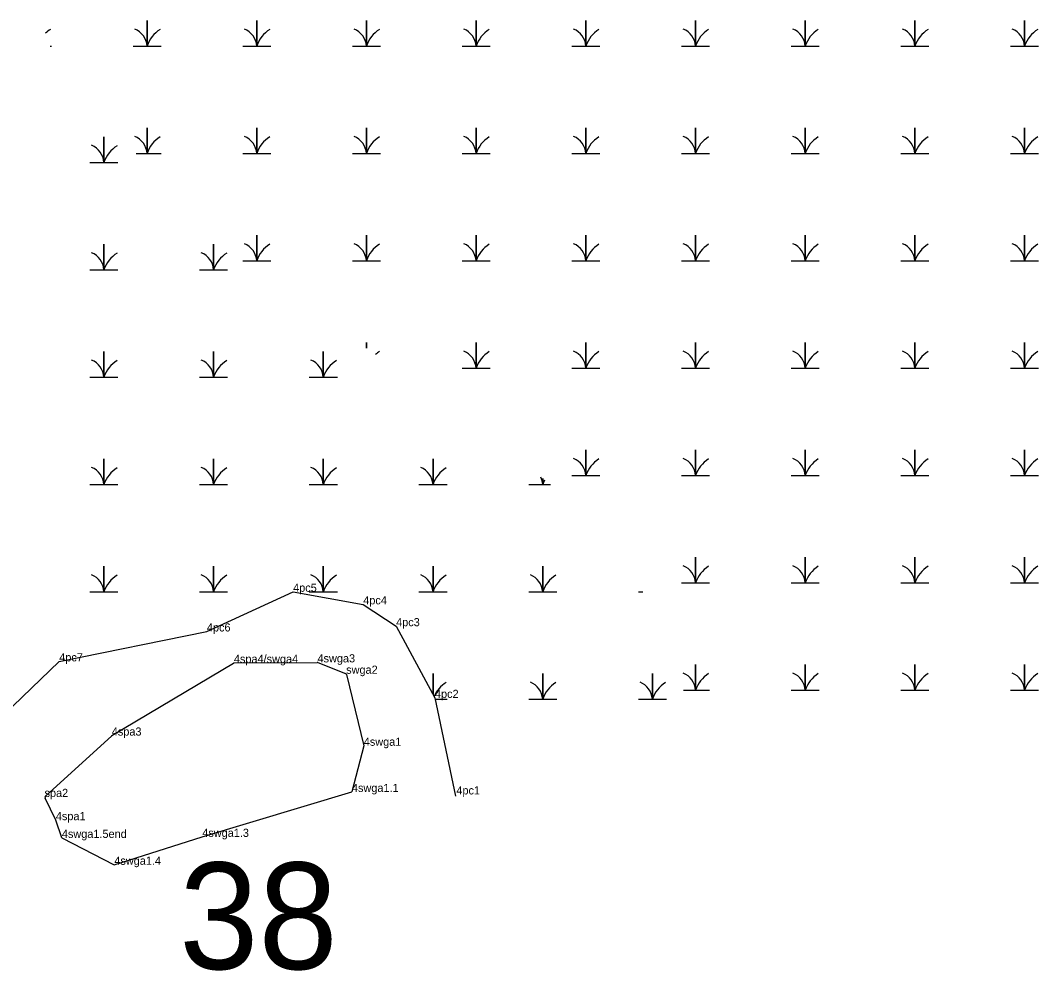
# Model space of a CAD drawing. Extents: x 2072529 to 2268796, y 436423 to 470397.
# Drawn here: x 2104808 to 2105432, y 455716 to 456299 of the extents above; entities that cross this region are included whole.
import ezdxf

# ---------------------------------------------------------------- set-up
doc = ezdxf.new("R2010")
doc.units = 0
for name, color, linetype in [('Default', 7, 'Continuous'), ('Exist Environmental Wetland Boundary', 7, 'Continuous'), ('Exist Environmental Wetland Boundary Cogo Comment', 7, 'Continuous'), ('Exist Environmental Wetland Boundary Cogo Point CELL', 7, 'Continuous'), ('Exist Hydro Jurisdictional Stream or Body of Water NEU Mitigable', 7, 'Continuous'), ('Exist Hydro Jurisdictional Stream or Body of Water NEU Mitigable Cogo Comment', 7, 'Continuous'), ('Exist Hydro Swamp or Marsh', 7, 'Continuous')]:
    doc.layers.add(name, color=color, linetype=linetype)

msp = doc.modelspace()

# ---------------------------------------------------------------- linework, layer by layer
at = {"layer": 'Exist Environmental Wetland Boundary'}
msp.add_lwpolyline([(2104609.24, 455735.62), (2104621.06, 455780.18), (2104644.33, 455777.94), (2104722.37, 455817.34), (2104735.27, 455837.55), (2104752.11, 455850.33), (2104763.03, 455846.4), (2104748.18, 455876.1), (2104755.02, 455879.71), (2104763.33, 455856.41), (2104791.87, 455867.62), (2104831.75, 455905.88), (2104922.28, 455924.22), (2104975.15, 455948.56), (2105018.14, 455940.86), (2105038.3, 455927.43), (2105062.1, 455883.49), (2105074.69, 455823.25)], dxfattribs=at)
at = {"layer": 'Exist Environmental Wetland Boundary Cogo Point CELL'}
for p, q in [((2104975.15, 455948.56), (2104975.15, 455948.56)), ((2105018.14, 455940.86), (2105018.14, 455940.86)), ((2104922.28, 455924.22), (2104922.28, 455924.22)), ((2105038.3, 455927.43), (2105038.3, 455927.43)), ((2104831.75, 455905.88), (2104831.75, 455905.88)), ((2104938.82, 455904.92), (2104938.82, 455904.92)), ((2104990.09, 455905.27), (2104990.09, 455905.27)), ((2105007.67, 455898.3), (2105007.67, 455898.3)), ((2105062.1, 455883.49), (2105062.1, 455883.49)), ((2104863.97, 455860.4), (2104863.97, 455860.4)), ((2105018.46, 455854.16), (2105018.46, 455854.16)), ((2104822.73, 455822.78), (2104822.73, 455822.78)), ((2105011.2, 455825.84), (2105011.2, 455825.84)), ((2105074.69, 455823.25), (2105074.69, 455823.25)), ((2104829.66, 455808.56), (2104829.66, 455808.56)), ((2104833.36, 455797.69), (2104833.36, 455797.69)), ((2104919.44, 455798.31), (2104919.44, 455798.31)), ((2104865.51, 455781.23), (2104865.51, 455781.23))]:
    msp.add_line(p, q, dxfattribs=at)
at = {"layer": 'Exist Hydro Jurisdictional Stream or Body of Water NEU Mitigable'}
for p, q in [((2104864.06, 455860.45), (2104938.59, 455904.78)), ((2104939.09, 455904.92), (2104989.9, 455905.26)), ((2104990.27, 455905.19), (2105007.19, 455898.49)), ((2104823.29, 455823.28), (2104863.9, 455860.33))]:
    msp.add_line(p, q, dxfattribs=at)
for points in [[(2105007.79, 455897.8), (2105018.46, 455854.16), (2105011.2, 455825.84)], [(2104833.36, 455797.69), (2104865.51, 455781.23), (2104919.44, 455798.31), (2105011.2, 455825.84)], [(2104833.36, 455797.69), (2104829.66, 455808.56), (2104823.06, 455822.1)]]:
    msp.add_lwpolyline(points, dxfattribs=at)
for centre, start, end in [((2104939.1, 455903.92), 90.38443, 120.74544), ((2104989.9, 455904.26), 68.39894, 90.38443), ((2105006.82, 455897.57), 13.73502, 68.39894), ((2104864.57, 455859.59), 120.74544, 132.37312), ((2104823.96, 455822.54), 132.37312, 205.98818)]:
    msp.add_arc(centre, 1, start, end, dxfattribs=at)
at = {"layer": 'Exist Hydro Swamp or Marsh'}
for points in [[(2104877.01, 456283.01), (2104885.61, 456283.01), (2104885.61, 456298.79), (2104885.61, 456283.01), (2104894.22, 456283.01)], [(2104944.26, 456283.01), (2104952.86, 456283.01), (2104952.86, 456298.79), (2104952.86, 456283.01), (2104961.47, 456283.01)], [(2105011.51, 456283.01), (2105020.11, 456283.01), (2105020.11, 456298.79), (2105020.11, 456283.01), (2105028.72, 456283.01)], [(2105078.76, 456283.01), (2105087.36, 456283.01), (2105087.36, 456298.79), (2105087.36, 456283.01), (2105095.97, 456283.01)], [(2105146.01, 456283.01), (2105154.61, 456283.01), (2105154.61, 456298.79), (2105154.61, 456283.01), (2105163.22, 456283.01)], [(2105213.26, 456283.01), (2105221.86, 456283.01), (2105221.86, 456298.79), (2105221.86, 456283.01), (2105230.47, 456283.01)], [(2105280.51, 456283.01), (2105289.11, 456283.01), (2105289.11, 456298.79), (2105289.11, 456283.01), (2105297.72, 456283.01)], [(2105347.76, 456283.01), (2105356.36, 456283.01), (2105356.36, 456298.79), (2105356.36, 456283.01), (2105364.97, 456283.01)], [(2105415.01, 456283.01), (2105423.61, 456283.01), (2105423.61, 456298.79), (2105423.61, 456283.01), (2105432.22, 456283.01)], [(2104826.22, 456283.01), (2104826.97, 456283.01)], [(2104878.87, 456217.21), (2104885.61, 456217.21), (2104885.61, 456232.99), (2104885.61, 456217.21), (2104894.22, 456217.21)], [(2104944.26, 456217.21), (2104952.86, 456217.21), (2104952.86, 456232.99), (2104952.86, 456217.21), (2104961.47, 456217.21)], [(2105011.51, 456217.21), (2105020.11, 456217.21), (2105020.11, 456232.99), (2105020.11, 456217.21), (2105028.72, 456217.21)], [(2105078.76, 456217.21), (2105087.36, 456217.21), (2105087.36, 456232.99), (2105087.36, 456217.21), (2105095.97, 456217.21)], [(2105146.01, 456217.21), (2105154.61, 456217.21), (2105154.61, 456232.99), (2105154.61, 456217.21), (2105163.22, 456217.21)], [(2105213.26, 456217.21), (2105221.86, 456217.21), (2105221.86, 456232.99), (2105221.86, 456217.21), (2105230.47, 456217.21)], [(2105280.51, 456217.21), (2105289.11, 456217.21), (2105289.11, 456232.99), (2105289.11, 456217.21), (2105297.72, 456217.21)], [(2105347.76, 456217.21), (2105356.36, 456217.21), (2105356.36, 456232.99), (2105356.36, 456217.21), (2105364.97, 456217.21)], [(2105415.01, 456217.21), (2105423.61, 456217.21), (2105423.61, 456232.99), (2105423.61, 456217.21), (2105432.22, 456217.21)], [(2104850.56, 456211.72), (2104859.16, 456211.72), (2104859.16, 456227.5), (2104859.16, 456211.72), (2104867.76, 456211.72)], [(2104944.26, 456151.41), (2104952.86, 456151.41), (2104952.86, 456167.19), (2104952.86, 456151.41), (2104961.47, 456151.41)], [(2105011.51, 456151.41), (2105020.11, 456151.41), (2105020.11, 456167.19), (2105020.11, 456151.41), (2105028.72, 456151.41)], [(2105078.76, 456151.41), (2105087.36, 456151.41), (2105087.36, 456167.19), (2105087.36, 456151.41), (2105095.97, 456151.41)], [(2105146.01, 456151.41), (2105154.61, 456151.41), (2105154.61, 456167.19), (2105154.61, 456151.41), (2105163.22, 456151.41)], [(2105213.26, 456151.41), (2105221.86, 456151.41), (2105221.86, 456167.19), (2105221.86, 456151.41), (2105230.47, 456151.41)], [(2105280.51, 456151.41), (2105289.11, 456151.41), (2105289.11, 456167.19), (2105289.11, 456151.41), (2105297.72, 456151.41)], [(2105347.76, 456151.41), (2105356.36, 456151.41), (2105356.36, 456167.19), (2105356.36, 456151.41), (2105364.97, 456151.41)], [(2105415.01, 456151.41), (2105423.61, 456151.41), (2105423.61, 456167.19), (2105423.61, 456151.41), (2105432.22, 456151.41)], [(2104850.56, 456145.92), (2104859.16, 456145.92), (2104859.16, 456161.7), (2104859.16, 456145.92), (2104867.76, 456145.92)], [(2104917.81, 456145.92), (2104926.41, 456145.92), (2104926.41, 456161.7), (2104926.41, 456145.92), (2104935.01, 456145.92)], [(2105020.11, 456097.82), (2105020.11, 456101.39), (2105020.11, 456097.82)], [(2105078.76, 456085.61), (2105087.36, 456085.61), (2105087.36, 456101.39), (2105087.36, 456085.61), (2105095.97, 456085.61)], [(2105146.01, 456085.61), (2105154.61, 456085.61), (2105154.61, 456101.39), (2105154.61, 456085.61), (2105163.22, 456085.61)], [(2105213.26, 456085.61), (2105221.86, 456085.61), (2105221.86, 456101.39), (2105221.86, 456085.61), (2105230.47, 456085.61)], [(2105280.51, 456085.61), (2105289.11, 456085.61), (2105289.11, 456101.39), (2105289.11, 456085.61), (2105297.72, 456085.61)], [(2105347.76, 456085.61), (2105356.36, 456085.61), (2105356.36, 456101.39), (2105356.36, 456085.61), (2105364.97, 456085.61)], [(2105415.01, 456085.61), (2105423.61, 456085.61), (2105423.61, 456101.39), (2105423.61, 456085.61), (2105432.22, 456085.61)], [(2104850.56, 456080.12), (2104859.16, 456080.12), (2104859.16, 456095.9), (2104859.16, 456080.12), (2104867.76, 456080.12)], [(2104917.81, 456080.12), (2104926.41, 456080.12), (2104926.41, 456095.9), (2104926.41, 456080.12), (2104935.01, 456080.12)], [(2104985.06, 456080.12), (2104993.66, 456080.12), (2104993.66, 456095.9), (2104993.66, 456080.12), (2105002.26, 456080.12)], [(2105146.01, 456019.81), (2105154.61, 456019.81), (2105154.61, 456035.59), (2105154.61, 456019.81), (2105163.22, 456019.81)], [(2105213.26, 456019.81), (2105221.86, 456019.81), (2105221.86, 456035.59), (2105221.86, 456019.81), (2105230.47, 456019.81)], [(2105280.51, 456019.81), (2105289.11, 456019.81), (2105289.11, 456035.59), (2105289.11, 456019.81), (2105297.72, 456019.81)], [(2105347.76, 456019.81), (2105356.36, 456019.81), (2105356.36, 456035.59), (2105356.36, 456019.81), (2105364.97, 456019.81)], [(2105415.01, 456019.81), (2105423.61, 456019.81), (2105423.61, 456035.59), (2105423.61, 456019.81), (2105432.22, 456019.81)], [(2104850.56, 456014.32), (2104859.16, 456014.32), (2104859.16, 456030.1), (2104859.16, 456014.32), (2104867.76, 456014.32)], [(2104917.81, 456014.32), (2104926.41, 456014.32), (2104926.41, 456030.1), (2104926.41, 456014.32), (2104935.01, 456014.32)], [(2104985.06, 456014.32), (2104993.66, 456014.32), (2104993.66, 456030.1), (2104993.66, 456014.32), (2105002.26, 456014.32)], [(2105052.31, 456014.32), (2105060.91, 456014.32), (2105060.91, 456030.1), (2105060.91, 456014.32), (2105069.51, 456014.32)], [(2105119.56, 456014.32), (2105128.16, 456014.32), (2105128.16, 456017.89)], [(2105128.16, 456017.89), (2105128.16, 456014.32), (2105132.98, 456014.32)], [(2105213.26, 455954.01), (2105221.86, 455954.01), (2105221.86, 455969.79), (2105221.86, 455954.01), (2105230.47, 455954.01)], [(2105280.51, 455954.01), (2105289.11, 455954.01), (2105289.11, 455969.79), (2105289.11, 455954.01), (2105297.72, 455954.01)], [(2105347.76, 455954.01), (2105356.36, 455954.01), (2105356.36, 455969.79), (2105356.36, 455954.01), (2105364.97, 455954.01)], [(2105415.01, 455954.01), (2105423.61, 455954.01), (2105423.61, 455969.79), (2105423.61, 455954.01), (2105432.22, 455954.01)], [(2104850.56, 455948.52), (2104859.16, 455948.52), (2104859.16, 455964.3), (2104859.16, 455948.52), (2104867.76, 455948.52)], [(2104917.81, 455948.52), (2104926.41, 455948.52), (2104926.41, 455964.3), (2104926.41, 455948.52), (2104935.01, 455948.52)], [(2104985.06, 455948.52), (2104993.66, 455948.52), (2104993.66, 455964.3), (2104993.66, 455948.52), (2105002.26, 455948.52)], [(2105052.31, 455948.52), (2105060.91, 455948.52), (2105060.91, 455964.3), (2105060.91, 455948.52), (2105069.51, 455948.52)], [(2105119.56, 455948.52), (2105128.16, 455948.52), (2105128.16, 455964.3), (2105128.16, 455948.52), (2105136.76, 455948.52)], [(2105186.81, 455948.52), (2105189.64, 455948.52)], [(2105214.56, 455888.21), (2105221.86, 455888.21), (2105221.86, 455903.99), (2105221.86, 455888.21), (2105230.47, 455888.21)], [(2105280.51, 455888.21), (2105289.11, 455888.21), (2105289.11, 455903.99), (2105289.11, 455888.21), (2105297.72, 455888.21)], [(2105347.76, 455888.21), (2105356.36, 455888.21), (2105356.36, 455903.99), (2105356.36, 455888.21), (2105364.97, 455888.21)], [(2105415.01, 455888.21), (2105423.61, 455888.21), (2105423.61, 455903.99), (2105423.61, 455888.21), (2105432.22, 455888.21)], [(2105060.91, 455885.69), (2105060.91, 455898.5), (2105060.91, 455885.69)], [(2105119.56, 455882.72), (2105128.16, 455882.72), (2105128.16, 455898.5), (2105128.16, 455882.72), (2105136.76, 455882.72)], [(2105186.81, 455882.72), (2105195.41, 455882.72), (2105195.41, 455898.5), (2105195.41, 455882.72), (2105204.01, 455882.72)], [(2105062.26, 455882.72), (2105069.51, 455882.72)]]:
    msp.add_lwpolyline(points, dxfattribs=at)
for centre, radius, start, end in [((2104836.61, 456276.95), 19.22, 122.12745, 133.51645), ((2104873.35, 456282.12), 12.3, 4.14034, 67.53497), ((2104903.86, 456276.95), 19.22, 122.12745, 161.62219), ((2104940.6, 456282.12), 12.3, 4.14034, 67.53497), ((2104971.11, 456276.95), 19.22, 122.12745, 161.62219), ((2105007.85, 456282.12), 12.3, 4.14034, 67.53497), ((2105038.36, 456276.95), 19.22, 122.12745, 161.62219), ((2105075.1, 456282.12), 12.3, 4.14034, 67.53497), ((2105105.61, 456276.95), 19.22, 122.12745, 161.62219), ((2105142.35, 456282.12), 12.3, 4.14034, 67.53497), ((2105172.86, 456276.95), 19.22, 122.12745, 161.62219), ((2105209.6, 456282.12), 12.3, 4.14034, 67.53497), ((2105240.11, 456276.95), 19.22, 122.12745, 161.62219), ((2105276.85, 456282.12), 12.3, 4.14034, 67.53497), ((2105307.36, 456276.95), 19.22, 122.12745, 161.62219), ((2105344.1, 456282.12), 12.3, 4.14034, 67.53497), ((2105374.61, 456276.95), 19.22, 122.12745, 161.62219), ((2105411.35, 456282.12), 12.3, 4.14034, 67.53497), ((2105441.86, 456276.95), 19.22, 122.12745, 161.62219), ((2104846.9, 456210.83), 12.3, 4.14034, 67.53497), ((2104877.41, 456205.66), 19.22, 122.12745, 161.62219), ((2104873.35, 456216.32), 12.3, 4.14034, 67.53497), ((2104903.86, 456211.15), 19.22, 122.12745, 161.62219), ((2104940.6, 456216.32), 12.3, 4.14034, 67.53497), ((2104971.11, 456211.15), 19.22, 122.12745, 161.62219), ((2105007.85, 456216.32), 12.3, 4.14034, 67.53497), ((2105038.36, 456211.15), 19.22, 122.12745, 161.62219), ((2105075.1, 456216.32), 12.3, 4.14034, 67.53497), ((2105105.61, 456211.15), 19.22, 122.12745, 161.62219), ((2105142.35, 456216.32), 12.3, 4.14034, 67.53497), ((2105172.86, 456211.15), 19.22, 122.12745, 161.62219), ((2105209.6, 456216.32), 12.3, 4.14034, 67.53497), ((2105240.11, 456211.15), 19.22, 122.12745, 161.62219), ((2105276.85, 456216.32), 12.3, 4.14034, 67.53497), ((2105307.36, 456211.15), 19.22, 122.12745, 161.62219), ((2105344.1, 456216.32), 12.3, 4.14034, 67.53497), ((2105374.61, 456211.15), 19.22, 122.12745, 161.62219), ((2105411.35, 456216.32), 12.3, 4.14034, 67.53497), ((2105441.86, 456211.15), 19.22, 122.12745, 161.62219), ((2104940.6, 456150.52), 12.3, 4.14034, 67.53497), ((2104971.11, 456145.35), 19.22, 122.12745, 161.62219), ((2105007.85, 456150.52), 12.3, 4.14034, 67.53497), ((2105038.36, 456145.35), 19.22, 122.12745, 161.62219), ((2105075.1, 456150.52), 12.3, 4.14034, 67.53497), ((2105105.61, 456145.35), 19.22, 122.12745, 161.62219), ((2105142.35, 456150.52), 12.3, 4.14034, 67.53497), ((2105172.86, 456145.35), 19.22, 122.12745, 161.62219), ((2105209.6, 456150.52), 12.3, 4.14034, 67.53497), ((2105240.11, 456145.35), 19.22, 122.12745, 161.62219), ((2105276.85, 456150.52), 12.3, 4.14034, 67.53497), ((2105307.36, 456145.35), 19.22, 122.12745, 161.62219), ((2105344.1, 456150.52), 12.3, 4.14034, 67.53497), ((2105374.61, 456145.35), 19.22, 122.12745, 161.62219), ((2105411.35, 456150.52), 12.3, 4.14034, 67.53497), ((2105441.86, 456145.35), 19.22, 122.12745, 161.62219), ((2104846.9, 456145.03), 12.3, 4.14034, 67.53497), ((2104877.41, 456139.86), 19.22, 122.12745, 161.62219), ((2104914.15, 456145.03), 12.3, 4.14034, 67.53497), ((2104944.66, 456139.86), 19.22, 122.12745, 161.62219), ((2104846.9, 456079.23), 12.3, 4.14034, 67.53497), ((2104914.15, 456079.23), 12.3, 4.14034, 67.53497), ((2104981.4, 456079.23), 12.3, 4.14034, 67.53497), ((2105038.36, 456079.55), 19.22, 122.12745, 131.4452), ((2105075.1, 456084.72), 12.3, 4.14034, 67.53497), ((2105105.61, 456079.55), 19.22, 122.12745, 161.62219), ((2105142.35, 456084.72), 12.3, 4.14034, 67.53497), ((2105172.86, 456079.55), 19.22, 122.12745, 161.62219), ((2105209.6, 456084.72), 12.3, 4.14034, 67.53497), ((2105240.11, 456079.55), 19.22, 122.12745, 161.62219), ((2105276.85, 456084.72), 12.3, 4.14034, 67.53497), ((2105307.36, 456079.55), 19.22, 122.12745, 161.62219), ((2105344.1, 456084.72), 12.3, 4.14034, 67.53497), ((2105374.61, 456079.55), 19.22, 122.12745, 161.62219), ((2105411.35, 456084.72), 12.3, 4.14034, 67.53497), ((2105441.86, 456079.55), 19.22, 122.12745, 161.62219), ((2104877.41, 456074.06), 19.22, 122.12745, 161.62219), ((2104944.66, 456074.06), 19.22, 122.12745, 161.62219), ((2105011.91, 456074.06), 19.22, 122.12745, 161.62219), ((2105142.35, 456018.92), 12.3, 4.14034, 67.53497), ((2105172.86, 456013.75), 19.22, 122.12745, 161.62219), ((2105209.6, 456018.92), 12.3, 4.14034, 67.53497), ((2105240.11, 456013.75), 19.22, 122.12745, 161.62219), ((2105276.85, 456018.92), 12.3, 4.14034, 67.53497), ((2105307.36, 456013.75), 19.22, 122.12745, 161.62219), ((2105344.1, 456018.92), 12.3, 4.14034, 67.53497), ((2105374.61, 456013.75), 19.22, 122.12745, 161.62219), ((2105411.35, 456018.92), 12.3, 4.14034, 67.53497), ((2105441.86, 456013.75), 19.22, 122.12745, 161.62219), ((2104846.9, 456013.43), 12.3, 4.14034, 67.53497), ((2104877.41, 456008.26), 19.22, 122.12745, 161.62219), ((2104914.15, 456013.43), 12.3, 4.14034, 67.53497), ((2104944.66, 456008.26), 19.22, 122.12745, 161.62219), ((2104981.4, 456013.43), 12.3, 4.14034, 67.53497), ((2105011.91, 456008.26), 19.22, 122.12745, 161.62219), ((2105048.65, 456013.43), 12.3, 4.14034, 67.53497), ((2105079.16, 456008.26), 19.22, 122.12745, 161.62219), ((2105115.9, 456013.43), 12.3, 4.14034, 25.73763), ((2105146.41, 456008.26), 19.22, 152.81116, 161.62219), ((2105209.6, 455953.12), 12.3, 4.14034, 67.53497), ((2105240.11, 455947.95), 19.22, 122.12745, 161.62219), ((2105276.85, 455953.12), 12.3, 4.14034, 67.53497), ((2105307.36, 455947.95), 19.22, 122.12745, 161.62219), ((2105344.1, 455953.12), 12.3, 4.14034, 67.53497), ((2105374.61, 455947.95), 19.22, 122.12745, 161.62219), ((2105411.35, 455953.12), 12.3, 4.14034, 67.53497), ((2105441.86, 455947.95), 19.22, 122.12745, 161.62219), ((2104846.9, 455947.63), 12.3, 4.14034, 67.53497), ((2104877.41, 455942.46), 19.22, 122.12745, 161.62219), ((2104914.15, 455947.63), 12.3, 4.14034, 67.53497), ((2104944.66, 455942.46), 19.22, 122.12745, 161.62219), ((2104981.4, 455947.63), 12.3, 4.14034, 67.53497), ((2105011.91, 455942.46), 19.22, 122.12745, 161.62219), ((2105048.65, 455947.63), 12.3, 4.14034, 67.53497), ((2105079.16, 455942.46), 19.22, 122.12745, 161.62219), ((2105115.9, 455947.63), 12.3, 4.14034, 67.53497), ((2105146.41, 455942.46), 19.22, 122.12745, 161.62219), ((2105209.6, 455887.32), 12.3, 4.14034, 67.53497), ((2105240.11, 455882.15), 19.22, 122.12745, 161.62219), ((2105276.85, 455887.32), 12.3, 4.14034, 67.53497), ((2105307.36, 455882.15), 19.22, 122.12745, 161.62219), ((2105344.1, 455887.32), 12.3, 4.14034, 67.53497), ((2105374.61, 455882.15), 19.22, 122.12745, 161.62219), ((2105411.35, 455887.32), 12.3, 4.14034, 67.53497), ((2105441.86, 455882.15), 19.22, 122.12745, 161.62219), ((2105079.16, 455876.66), 19.22, 122.12745, 156.09006), ((2105115.9, 455881.83), 12.3, 4.14034, 67.53497), ((2105146.41, 455876.66), 19.22, 122.12745, 161.62219), ((2105183.15, 455881.83), 12.3, 4.14034, 67.53497), ((2105213.66, 455876.66), 19.22, 122.12745, 161.62219)]:
    msp.add_arc(centre, radius, start, end, dxfattribs=at)

# ---------------------------------------------------------------- texts
at = {"layer": 'Default'}
msp.add_text('38', height=65.34, dxfattribs=at).set_placement((2104905.31, 455717.28))
at = {"layer": 'Exist Environmental Wetland Boundary Cogo Comment'}
for s, p in [('4pc5', (2104975.15, 455948.56)), ('4pc4', (2105018.14, 455940.86)), ('4pc6', (2104922.28, 455924.22)), ('4pc3', (2105038.3, 455927.43)), ('4pc7', (2104831.75, 455905.88)), ('4pc2', (2105062.1, 455883.49)), ('4pc1', (2105075.24, 455824.34))]:
    msp.add_text(s, height=5, dxfattribs=at).set_placement(p)
at = {"layer": 'Exist Hydro Jurisdictional Stream or Body of Water NEU Mitigable Cogo Comment'}
for s, p in [('4spa4/swga4', (2104938.82, 455904.92)), ('4swga3', (2104990.09, 455905.27)), ('swga2', (2105007.67, 455898.3)), ('4spa3', (2104863.97, 455860.4)), ('4swga1', (2105018.46, 455854.16)), ('4swga1.1', (2105011.2, 455825.84)), ('spa2', (2104822.73, 455822.78)), ('4spa1', (2104829.66, 455808.56)), ('4swga1.5end', (2104833.36, 455797.69)), ('4swga1.3', (2104919.44, 455798.31)), ('4swga1.4', (2104865.51, 455781.23))]:
    msp.add_text(s, height=5, dxfattribs=at).set_placement(p)

doc.saveas('drawing.dxf')
